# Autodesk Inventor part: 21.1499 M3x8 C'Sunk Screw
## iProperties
Created: 2007-03
Part Number: 21.1499 M3x8 C'Sunk Screw
Material: Steel, Mild
Description: Hexagon socket countersunk head cap screws
Document SubType Name: Modeling
Standard: DIN 7991
Designer: Andy Moles
Standards Organization: DIN
Language: en-US
Size Designation: M3x8
Categories: <MemberInstance Version="R10.0.0"><Categories><Category DisplayName="Fasteners" InternalName="e4da775c-781d-43d5-af7c-5136215cf5a6" Mnemonic="FSTN"><Category Di
Density: 7.86 g/cm^3
Author: Andy Moles
Revision Number: 1
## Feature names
1. Revolution1
2. Extrusion1
3. Fillet1
4. Chamfer1
